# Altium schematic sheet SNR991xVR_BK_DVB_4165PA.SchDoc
size A3
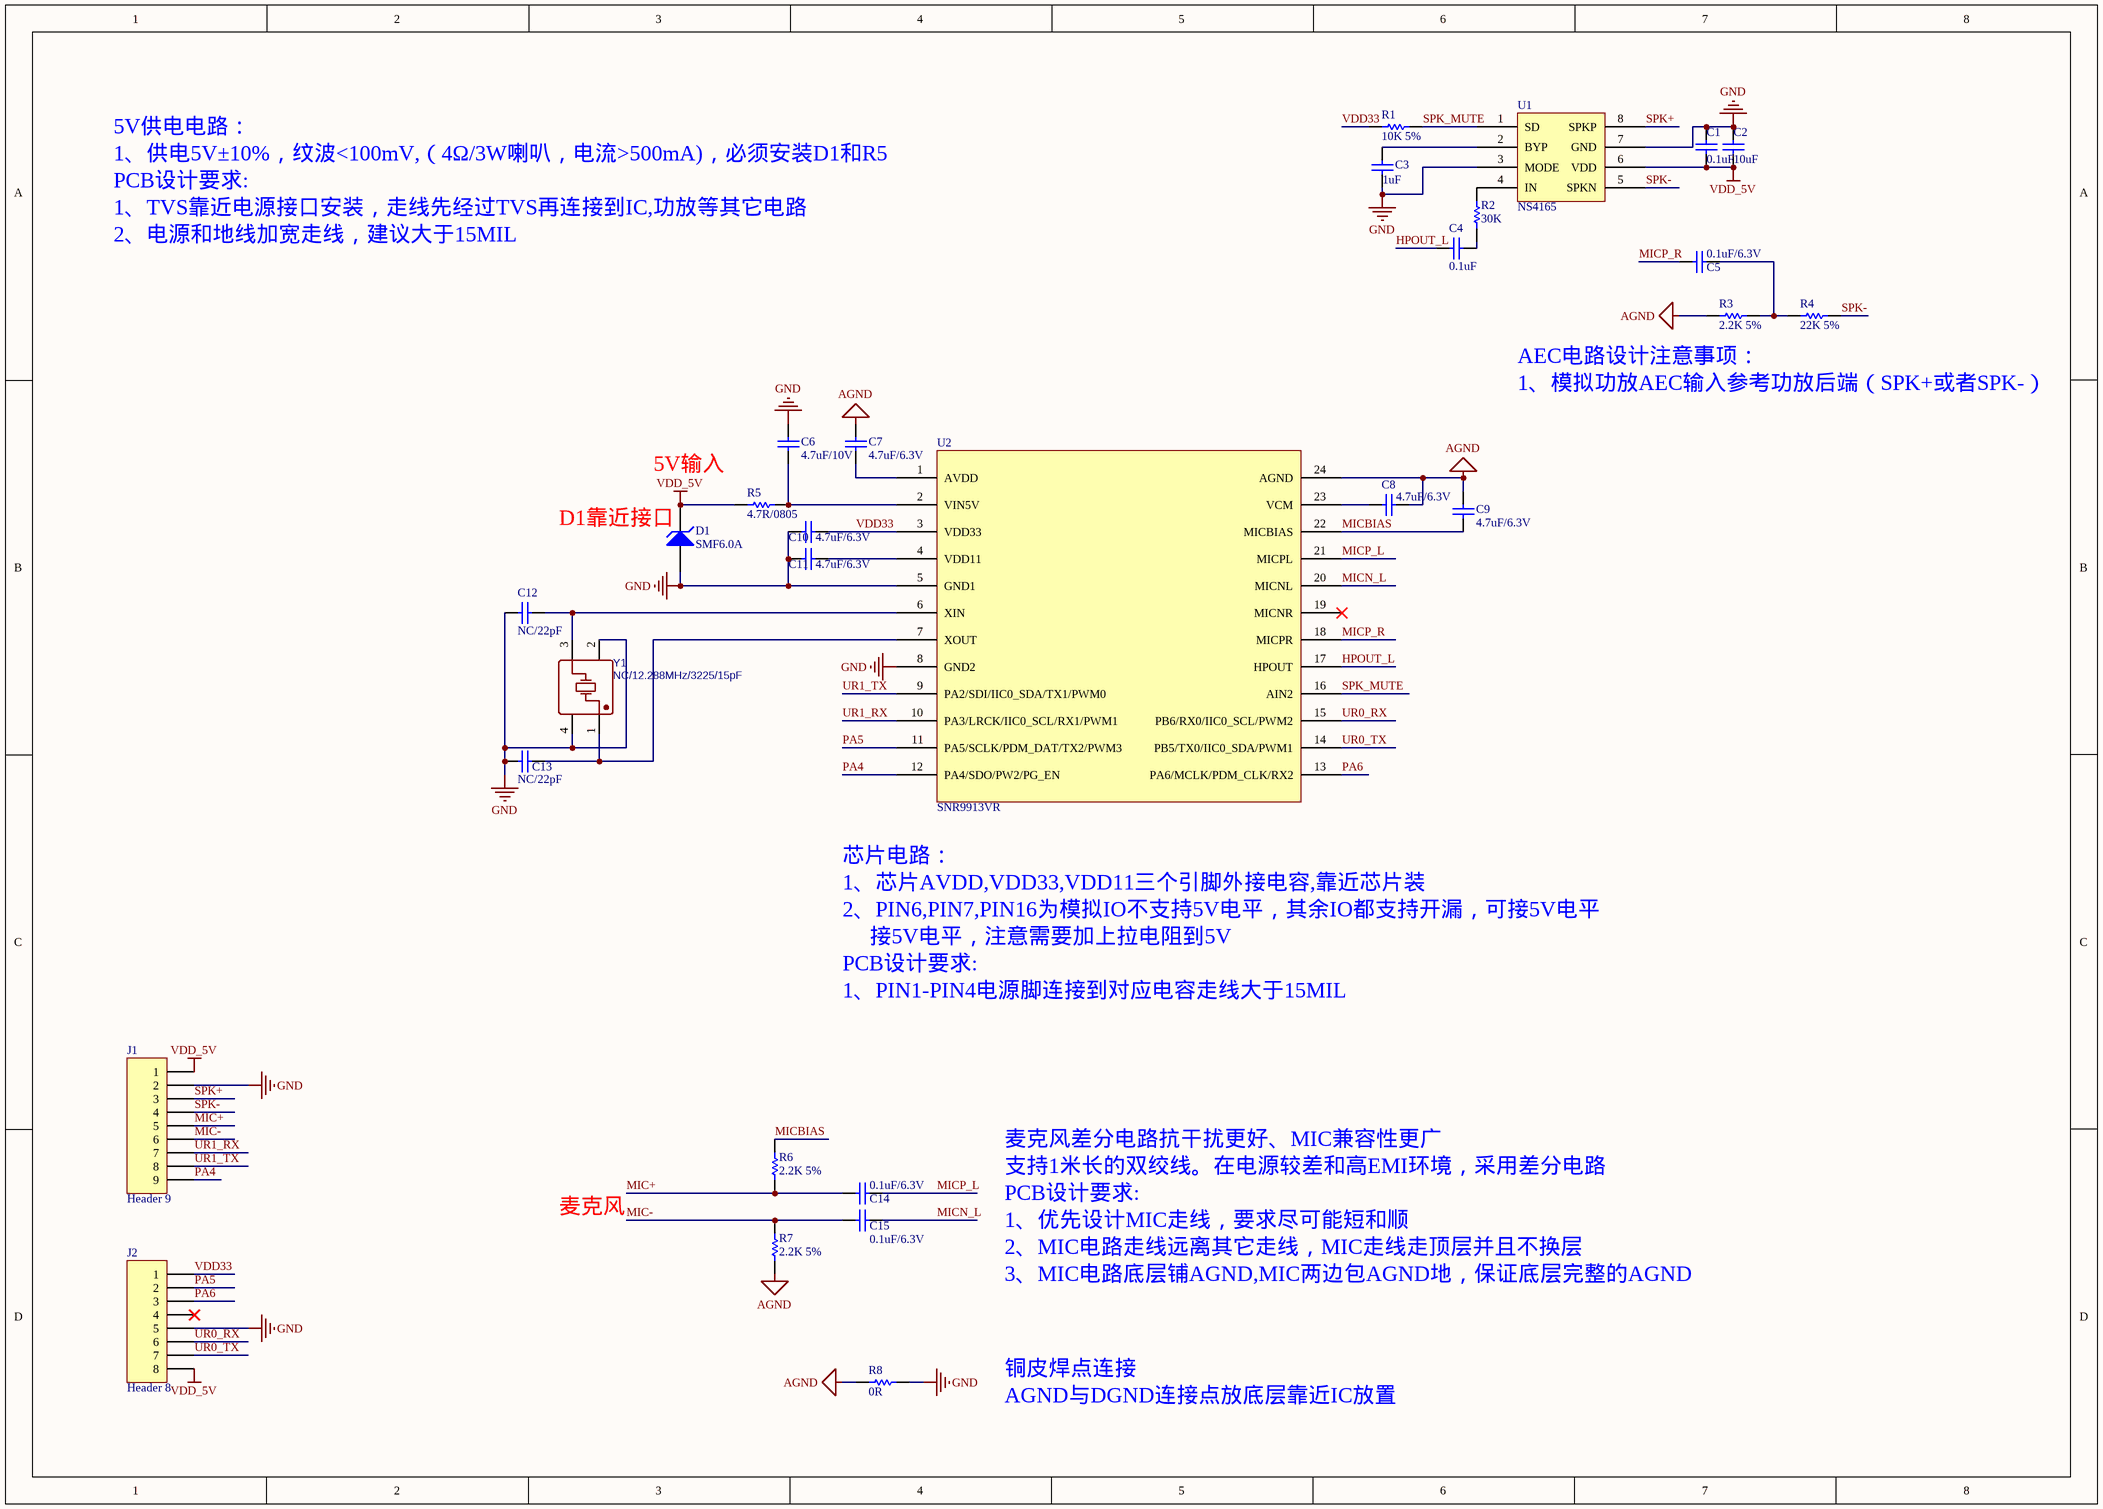
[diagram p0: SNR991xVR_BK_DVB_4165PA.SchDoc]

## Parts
C1  value 0.1uF  [C0402]  (hidden comment: Cap)
C2  value 10uF  [C0603]  (hidden comment: Cap)
C3  value 1uF  [C0402]  (hidden comment: Cap)
C4  value 0.1uF  [C0402]  (hidden comment: Cap)
C5  value 0.1uF/6.3V  [C0402]  (hidden comment: Cap)
C6  value 4.7uF/10V  [C0402]  (hidden comment: Cap)
C7  value 4.7uF/6.3V  [C0402]  (hidden comment: Cap)
C8  value 4.7uF/6.3V  [C0402]  (hidden comment: Cap)
C9  value 4.7uF/6.3V  [C0402]  (hidden comment: Cap)
C10  value 4.7uF/6.3V  [C0402]  (hidden comment: Cap)
C11  value 4.7uF/6.3V  [C0402]  (hidden comment: Cap)
C12  value NC/22pF  [C0402]  (hidden comment: Cap)
C13  value NC/22pF  [C0402]  (hidden comment: Cap)
C14  value 0.1uF/6.3V  [C0402]  (hidden comment: Cap)
C15  value 0.1uF/6.3V  [C0402]  (hidden comment: Cap)
D1  SMF6.0A  [SOD-123FL]
J1  Header 9  [HDR200M-1X9-YP]
J2  Header 8  [HDR200M-1X8-YP]
R1  value 10K 5%  [R0402]  (hidden comment: Res1)
R2  value 30K  [R0402]  (hidden comment: Res1)
R3  value 2.2K 5%  [R0402]  (hidden comment: Res1)
R4  value 22K 5%  [R0402]  (hidden comment: Res1)
R5  value 4.7R/0805  [R0805]  (hidden comment: Res1)
R6  value 2.2K 5%  [R0402]  (hidden comment: Res1)
R7  value 2.2K 5%  [R0402]  (hidden comment: Res1)
R8  value 0R  [SNR9912VR_R0R]  (hidden comment: Res1)
U1  NS4165  [NS4165]
U2  SNR9913VR  [SNR9912VR_24SSOP]
Y1  NC/12.288MHz/3225/15pF  [X4-3225]

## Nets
AGND: C7.1 C8.2 C9.1 R3.1 R7.2 R8.1 U2.24(AGND)
GND: C1.1 C2.2 C3.1 C6.1 C10.1 C11.1 C12.2 C13.2 D1.1(A) J1.2 J2.5 R8.2 U1.3(MODE) U1.7(GND) U2.5(GND1) U2.8(GND2) Y1.2(GND) Y1.4(GND)
VDD_5V: C1.2 C2.1 D1.2(K) J1.1 J2.8 R5.1 U1.6(VDD)
HPOUT_L: C4.1 U2.17(HPOUT)
MIC+: C14.2 J1.5 R6.2
MIC-: C15.2 J1.6 R7.1
MICBIAS: C9.2 R6.1 U2.22(MICBIAS)
MICN_L: C15.1 U2.20(MICNL)
MICP_L: C14.1 U2.21(MICPL)
MICP_R: C5.2 U2.18(MICPR)
PA4: J1.9 U2.12(PA4/SDO/PW2/PG_EN)
PA5: J2.2 U2.11(PA5/SCLK/PDM_DAT/TX2/PWM3)
PA6: J2.3 U2.13(PA6/MCLK/PDM_CLK/RX2)
SPK+: J1.3 U1.8(SPKP)
SPK-: J1.4 R4.2 U1.5(SPKN)
SPK_MUTE: R1.2 U1.1(SD) U2.16(AIN2)
UR0_RX: J2.6 U2.15(PB6/RX0/IIC0_SCL/PWM2)
UR0_TX: J2.7 U2.14(PB5/TX0/IIC0_SDA/PWM1)
UR1_RX: J1.7 U2.10(PA3/LRCK/IIC0_SCL/RX1/PWM1)
UR1_TX: J1.8 U2.9(PA2/SDI/IIC0_SDA/TX1/PWM0)
VDD33: C10.2 J2.1 R1.1 U2.3(VDD33)
NetC3_2: C3.2 U1.2(BYP)
NetC4_2: C4.2 R2.2
NetC5_1: C5.1 R3.2 R4.1
NetC6_2: C6.2 R5.2 U2.2(VIN5V)
NetC7_2: C7.2 U2.1(AVDD)
NetC8_1: C8.1 U2.23(VCM)
NetC11_2: C11.2 U2.4(VDD11)
NetC12_1: C12.1 U2.6(XIN) Y1.3(OUT)
NetC13_1: C13.1 U2.7(XOUT) Y1.1(OE#)
NetR2_1: R2.1 U1.4(IN)

Not connected (* = marked no-connect by the designer): J2 4*; U2 19(MICNR)*

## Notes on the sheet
- 5V供电电路：
- 1、供电5V±10%，纹波<100mV,（4Ω/3W喇叭，电流>500mA)，必须安装D1和R5
- PCB设计要求:
- 1、TVS靠近电源接口安装，走线先经过TVS再连接到IC,功放等其它电路
- 2、电源和地线加宽走线，建议大于15MIL
- AEC电路设计注意事项：
- 1、模拟功放AEC输入参考功放后端（SPK+或者SPK-）
- 5V输入
- D1靠近接口
- 芯片电路：
- 1、芯片AVDD,VDD33,VDD11三个引脚外接电容,靠近芯片装
- 2、PIN6,PIN7,PIN16为模拟IO不支持5V电平，其余IO都支持开漏，可接5V电平
- 接5V电平，注意需要加上拉电阻到5V
- 1、PIN1-PIN4电源脚连接到对应电容走线大于15MIL
- 麦克风差分电路抗干扰更好、MIC兼容性更广
- 支持1米长的双绞线。在电源较差和高EMI环境，采用差分电路
- 麦克风
- 1、优先设计MIC走线，要求尽可能短和顺
- 2、MIC电路走线远离其它走线，MIC走线走顶层并且不换层
- 3、MIC电路底层铺AGND,MIC两边包AGND地，保证底层完整的AGND
- 铜皮焊点连接
- AGND与DGND连接点放底层靠近IC放置

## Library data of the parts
C1-C15 = Cap: Capacitor
D1 = D Zener: Zener Diode
J1 = Header 9: Header, 9-Pin
J2 = Header 8: Header, 8-Pin
R1-R8 = Res1: Resistor
U2 = SNR9912VR
Y1 = 12.288MHz: BOM_Manufacturer: Zhejiang Abel Elec; BOM_Manufacturer Part: SMD-3225_4P 12.288MHZ 12PF; nameAlias: Frequency; Contributor: LCSC; SMT Type: Extend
